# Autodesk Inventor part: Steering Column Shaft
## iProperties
Shininess: 64.0
Length Units: 11269
Angle Units: 11279
Time Units: 11290
Mass Units: 11283
Length Display Precision: 3
Angle Display Precision: 2
Compacted: True
Part Number: Steering Column Shaft
Document SubType Name: Modeling
Created: 2004-03
Designer: rak
Manufacturer: Standard
Standards Organization: Custom
Density: 0.0
Volumn: 0.0
Area: 0.0
PropertySet Name: Model Information
Control State: 0
Master: False
Checked Out: False
Author: rak
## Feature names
1. Extrusion1
2. Extrusion2
3. Chamfer1
4. Fillet1
5. Hole1
